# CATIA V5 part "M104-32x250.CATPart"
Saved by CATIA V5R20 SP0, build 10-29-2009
Part number: M104-32x250
Source: Unknown
Bounding box of the stored display mesh (mm): x -15.868 to 15.868, y -15.868 to 15.868, z 0 to 250
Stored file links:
  C:\Users\Utente\Desktop\IO LAVORO\3D X SITO CF\X SITO\M104\M104-32x250.CATPart

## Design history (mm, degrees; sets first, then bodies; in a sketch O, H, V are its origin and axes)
Body1 (main body)
  Solid1 "PartBody": solid without history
